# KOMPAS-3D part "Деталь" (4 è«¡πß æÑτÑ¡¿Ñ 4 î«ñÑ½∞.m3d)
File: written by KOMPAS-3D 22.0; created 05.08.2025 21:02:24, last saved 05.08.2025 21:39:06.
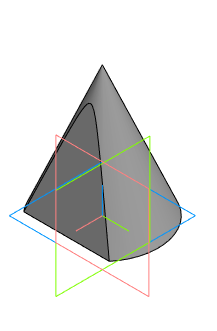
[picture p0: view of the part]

Document properties: Автор: user; Полное имя файла: G:\08 05 вторник\2025 НГ Лаб работы\Лаб 4 Сечение конуса\4 Модели\4 Конус Сечение 6 Модель.m3d

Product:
- Part/product: Деталь
    Масса: 0.468006

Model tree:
1. Эскиз:1
2. Элемент вращения:1
     Угол 1 = 360
3. Эскиз:2
4. Элемент выдавливания:2
     Расстояние 1 = 30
